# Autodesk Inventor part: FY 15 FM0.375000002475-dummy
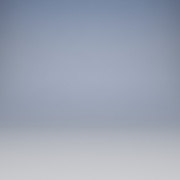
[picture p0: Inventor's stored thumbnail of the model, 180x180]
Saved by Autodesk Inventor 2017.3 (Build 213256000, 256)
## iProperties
Part Number: FY 15 FM0.375000002475-dummy
Material: Generic
Catalog Web Link: www.cadenas.de
Description: AYF_001HC_HH_HY-dummy-Y-bearing square flanged units
Vendor: SKF
Document SubType Name: Modeling
Designer: partserver
Manufacturer: SKF
Density: 1 g/cm^3
Appearance: PSOLRGB-175-175-175
Category: PARTsolutions
Company: SKF
Title: FY 15 FM0.375000002475-dummy
Author: Cadenas PARTsolutions
Comments: Y-bearing square flanged units
PSOL_IDENT_0: {$CADENAS_DATA\23d-libs\skf\bearings_units_and_housings\bearing_units\ball_bearing_units\y-units\y-b
PSOL_IDENT_1: earing_square_flanged_units_parts\ayf_001hc_hh_hy_dummy.prj},219 {VTYP=3D},{NB=FY 15 FM0.37500000247
PSOL_IDENT_2: 5-dummy},{LINA=FY 15 FM0.375000002475-dummy},{NN=AYF_001HC_HH_HY-dummy},{DATE=20.08.2020 13:45:20},{
PSOL_IDENT_3: GEOMDATE=30.07.2020 09:59:06},{VERSION=},{LINEID=52770},{WBVAR=COVER},{WBNUMERIC=}  {NB=FY 15 FM0.37
PSOL_IDENT_4: 5000002475-dummy},{LINA=FY 15 FM0.375000002475-dummy},{KT=DUMMY},{DESIGNATION=FY 15 FM},{HOUSING=FY
PSOL_IDENT_5: 503 M},{BEARING=YET 203/15},{COVER=},{DD=15},{DDX=},{DDALG=15.000},{DD1=24.200},{DD2=27.200},{DD3=},
PSOL_IDENT_6: {AALG=26.000},{A=26},{AX=},{AXX=},{A1ALG=11.000},{A1=11},{A1X=},{A1XX=},{A3ALG=3.200},{A3=3.2},{A3X=
PSOL_IDENT_7: },{A5ALG=0.000},{A5=},{A5X=},{A5XX=},{B=MIN},{B1=28.600},{B1X=},{B4ALG=4.750},{B4=},{B4X=4.75},{DAAA
PSOL_IDENT_8: LG=55.600},{DAA=55.6},{DAAX=},{DB=MIN},{DB1=50.000},{DB1X=},{DB2=53.000},{DB2X=},{HA=},{J=54.000},{J
PSOL_IDENT_9: X=},{JXX=},{L=76.000},{LX=},{LXX=},{N=11.500},{NX=},{NXX=},{SS1=22.100},{SS1X=},{T=39.600},{TX=},{DN=
PSOL_IDENT_10: 6.500},{SWN=7},{GN=1/4-28 SAE-LT},{RG=1/4-28 UNF},{RGX=},{R1=19},{R1X=},{J6=66},{J7=14.500},{N4=4},{
PSOL_IDENT_11: D=40.000},{C=12.000},{R12=0.300},{DW=6.747},{B3=13.500},{PITCH=28.500},{LOAD1=9.560},{LOAD2=4.750},{
PSOL_IDENT_12: LOAD3=0.200},{SPEED1=9500},{II=1},{Z=8},{MASS=0.400},{MASSX=},{G2=M6x0.75},{HKSGS=3},{RTTGS=4},{ALPH
PSOL_IDENT_13: A=},{GALG=10.000},{G=10},{GX=},{GXX=},{GINALG=0.375},{GIN=0.375000002475},{GINX=},{GINXX=},{EC=},{BS=
PSOL_IDENT_14: },{SLEEVE=},{POPULAR=},{D1=MIN},{K=1.3},{CC1=3.6},{BRGTYP=BBY_005},{COVERALG=  '', 'No end cover' },
PSOL_IDENT_15: {SUPPRESSED=unsuppressed},{TC=FY 15 FM}
NB: FY 15 FM0.375000002475-dummy
NN: AYF_001HC_HH_HY-dummy
NT: Y-bearing square flanged units
NBSYN: $TC.$GIN.-dummy
LINA: FY 15 FM0.375000002475-dummy
CATALOG: SKF
DESIGNATION: FY 15 FM
HOUSING: FY 503 M
BEARING: YET 203/15
COVER: No end cover
DD: 15
DD1: 24.2
DD2: 27.2
A: 26
A1: 11
A3: 3.2
B: 0
B1: 28.6
B4X: 4.75
DAA: 55.6
DB: 0
DB1: 50
DB2: 53
J: 54
L: 76
N: 11.5
SS1: 22.1
T: 39.6
DN: 6.5
SWN: 7
GN: 1/4-28 SAE-LT
RG: 1/4-28 UNF
R1: 19
J6: 66
J7: 14.5
N4: 4
D: 40
C: 12
R12: 0.3
DW: 6.747
B3: 13.5
PITCH: 28.5
LOAD1: 9.56
LOAD2: 4.75
LOAD3: 0.2
SPEED1: 9500
II: 1
Z: 8
MASS: 0.4
G2: M6x0.75
HKSGS: 3
RTTGS: 4
G: 10
GIN: 0.375000002475
D1: 0
K: 1.3
CC1: 3.6
BRGTYP: BBY_005
COVERALG: '', 'No end cover'
SUPPLIER: SKF
ARTICLENO: FY 15 FM0.375000002475-dummy
BOMINFO: FY 15 FM0.375000002475-dummy
CREATOR: CADENAS GmbH
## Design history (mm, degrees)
node "brg_XY"
node "brg_YZ"
node "brg_ZX"
node "brg_X"
node "brg_Y"
node "brg_Z"
node "brg_Center"
node "brg1_XY"
node "brg1_YZ"
node "brg1_ZX"
node "brg1_X"
node "brg1_Y"
node "brg1_Z"
node "brg1_Center"
node "dummy_XY"
node "dummy_YZ"
node "dummy_ZX"
node "dummy_X"
node "dummy_Y"
node "dummy_Z"
node "dummy_Center"
